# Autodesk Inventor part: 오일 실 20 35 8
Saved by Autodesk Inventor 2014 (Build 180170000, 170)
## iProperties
Created: 2026-01
Part Number: 오일 실 20 35 8
Material: 일반
Document SubType Name: Modeling
Designer: dg
Density: 1 g/cm^3
Appearance: 기본값
Author: dg
Author: jhkim
Description: 오일-실
Creation Date: 2026-01-09
Sending System: Autodesk Inventor 2026
Preprocessor: ST-DEVELOPER v20.1
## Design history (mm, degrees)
node "오일 실 20 35 81"
body "Solid1"
node "기준1"
